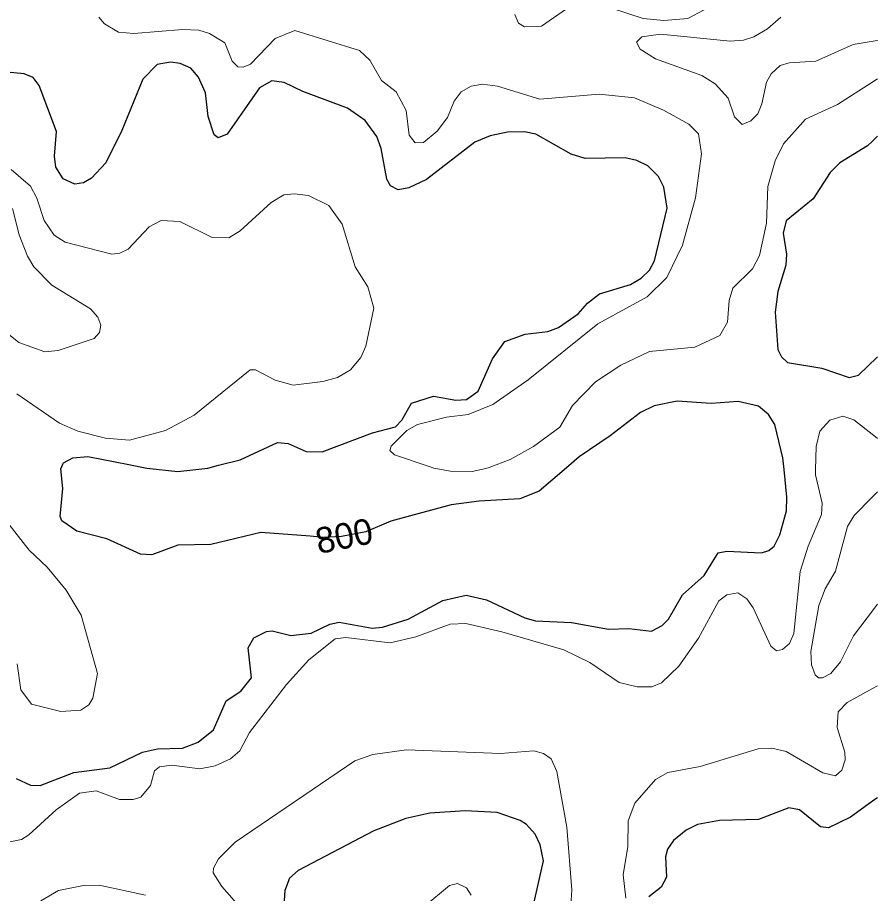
# Model space of a CAD drawing. Extents: x 473.9 to 500, y 7733.1 to 7760.8.
# Drawn here: x 497.324 to 500, y 7746.506 to 7749.235 of the extents above; entities that cross this region are included whole.
import ezdxf
from ezdxf.enums import TextEntityAlignment as Align

# ---------------------------------------------------------------- set-up
doc = ezdxf.new("R2010")
doc.units = 0
doc.header["$LTSCALE"] = 0.032
doc.layers.add('1', color=7, linetype='Continuous', lineweight=25)
doc.layers.add('2', color=7, linetype='Continuous', lineweight=13)
doc.layers.add('61', color=7, linetype='Continuous')

msp = doc.modelspace()

# ---------------------------------------------------------------- linework, layer by layer
at = {"layer": '1'}
for points in [[(498.5501, 7748.0341), (498.6184, 7748.0552), (498.6881, 7748.0425), (498.7206, 7748.0448), (498.7573, 7748.0715), (498.8019, 7748.1716), (498.8404, 7748.2256), (498.9036, 7748.2484), (498.9743, 7748.2573), (499.007, 7748.2694), (499.0683, 7748.3118), (499.0975, 7748.3454), (499.135, 7748.3746), (499.231, 7748.4035), (499.2642, 7748.4228), (499.2905, 7748.4477), (499.3063, 7748.4765), (499.3451, 7748.6413), (499.3349, 7748.7063), (499.3182, 7748.7392), (499.2848, 7748.7732), (499.2506, 7748.79), (499.2143, 7748.7974), (499.0906, 7748.7955), (499.0472, 7748.8097), (498.9367, 7748.8714), (498.9013, 7748.8786), (498.8484, 7748.8778), (498.7946, 7748.8663), (498.7464, 7748.8461), (498.5964, 7748.7308), (498.5417, 7748.7044), (498.5081, 7748.6981), (498.4845, 7748.7104), (498.4735, 7748.7311), (498.4556, 7748.8267), (498.4418, 7748.8647), (498.4053, 7748.9139), (498.3501, 7748.9525), (498.2112, 7749.0044), (498.1538, 7749.0324), (498.1156, 7749.0378), (498.0763, 7749.0163), (497.9761, 7748.8719), (497.9481, 7748.8606), (497.9357, 7748.8693), (497.917, 7748.927), (497.9089, 7748.9998), (497.8866, 7749.0491), (497.863, 7749.077), (497.8298, 7749.0918), (497.7995, 7749.0957), (497.7587, 7749.0885), (497.7139, 7749.043), (497.6485, 7748.8831), (497.5988, 7748.7822), (497.5538, 7748.734), (497.5285, 7748.7197), (497.5021, 7748.7156), (497.4654, 7748.7325), (497.4426, 7748.7687), (497.4389, 7748.803), (497.4446, 7748.8796), (497.3912, 7749.0233), (497.3719, 7749.0479), (497.3442, 7749.0592), (497.1383, 7749.0787)], [(500, 7748.8653), (499.9846, 7748.8499), (499.9694, 7748.8347), (499.8824, 7748.782), (499.8533, 7748.7524), (499.8002, 7748.6697), (499.7157, 7748.6016), (499.7069, 7748.5636), (499.7165, 7748.4973), (499.7143, 7748.4634), (499.6901, 7748.3817), (499.6821, 7748.3168), (499.6899, 7748.2007), (499.7011, 7748.1777), (499.7204, 7748.1606), (499.8272, 7748.1426), (499.9115, 7748.1141), (499.9412, 7748.1205), (499.9989, 7748.1768), (500, 7748.1779)], [(497.3198, 7746.8643), (497.3637, 7746.8436), (497.3945, 7746.8429), (497.4991, 7746.8838), (497.6111, 7746.8974), (497.713, 7746.9465), (497.7596, 7746.957), (497.8371, 7746.9592), (497.8863, 7746.9775), (497.9332, 7747.016), (497.9731, 7747.107), (498.0187, 7747.1364), (498.052, 7747.1785), (498.0413, 7747.2718), (498.0594, 7747.3031), (498.0985, 7747.3225), (498.1157, 7747.3243), (498.1739, 7747.3103), (498.2372, 7747.3173), (498.2954, 7747.345), (498.325, 7747.3517), (498.4274, 7747.3327), (498.4598, 7747.3359), (498.5391, 7747.361), (498.6478, 7747.4188), (498.7198, 7747.4361), (498.7829, 7747.4215), (498.9025, 7747.3655), (498.9361, 7747.356), (499.0473, 7747.3501), (499.1625, 7747.3301), (499.2258, 7747.3317), (499.2966, 7747.3235), (499.3302, 7747.341), (499.35, 7747.3605), (499.3933, 7747.4367), (499.4611, 7747.4966), (499.5043, 7747.5673), (499.5317, 7747.5729), (499.6388, 7747.5673), (499.6621, 7747.5746), (499.6785, 7747.5882), (499.6959, 7747.6233), (499.7174, 7747.6984), (499.7183, 7747.7405), (499.7095, 7747.8266), (499.7057, 7747.8636), (499.6809, 7747.9675), (499.6611, 7747.9982), (499.6302, 7748.0243), (499.5667, 7748.0391), (499.4829, 7748.0329), (499.3769, 7748.0396), (499.3046, 7748.0257), (499.2621, 7748.005), (499.1682, 7747.9316), (499.0719, 7747.866), (499.0317, 7747.8318), (498.9468, 7747.7597), (498.8873, 7747.7359), (498.7599, 7747.7289), (498.6731, 7747.7168), (498.4853, 7747.666), (498.4072, 7747.6331), (498.3322, 7747.6187), (498.2764, 7747.6148), (498.2345, 7747.6189), (498.0812, 7747.6308), (497.9255, 7747.5936), (497.8221, 7747.5915), (497.7416, 7747.5612), (497.7065, 7747.5633), (497.6011, 7747.6115), (497.5084, 7747.6349), (497.462, 7747.667), (497.4559, 7747.6807), (497.4645, 7747.7678), (497.4581, 7747.8287), (497.4646, 7747.8438), (497.4663, 7747.8478), (497.4958, 7747.8632), (497.5425, 7747.8679), (497.6701, 7747.8422), (497.7265, 7747.8309), (497.8225, 7747.8209), (497.9154, 7747.8316), (497.9496, 7747.8401), (498.0169, 7747.8568), (498.1325, 7747.9115), (498.1659, 7747.9082), (498.2217, 7747.8836), (498.2717, 7747.8826), (498.4281, 7747.9412), (498.5003, 7747.9602), (498.5195, 7747.9811), (498.5501, 7748.0341)], [(500, 7746.8047), (499.992, 7746.7989), (499.9156, 7746.7438), (499.8474, 7746.7113), (499.8227, 7746.7136), (499.757, 7746.7666), (499.7237, 7746.7729), (499.6295, 7746.7365), (499.5086, 7746.7335), (499.4397, 7746.7217), (499.4051, 7746.7037), (499.3653, 7746.6716), (499.3465, 7746.6449), (499.3406, 7746.6206), (499.3431, 7746.5572), (499.3263, 7746.5263), (499.2885, 7746.4964)], [(498.9159, 7746.4114), (498.9608, 7746.6081), (498.9502, 7746.6575), (498.9343, 7746.6917), (498.9082, 7746.721), (498.8885, 7746.7335), (498.8164, 7746.7587), (498.7167, 7746.764), (498.6067, 7746.757), (498.5326, 7746.7401), (498.4324, 7746.7016), (498.1974, 7746.5776), (498.1703, 7746.5541), (498.1559, 7746.5154), (498.1523, 7746.4693)]]:
    msp.add_lwpolyline(points, dxfattribs=at)
at = {"layer": '2'}
for points in [[(499.4609, 7749.259), (499.4101, 7749.232), (499.3353, 7749.2251), (499.2708, 7749.2323), (499.1244, 7749.2795)], [(499.0429, 7749.2694), (498.9543, 7749.2083), (498.9016, 7749.2054), (498.8832, 7749.2174), (498.8719, 7749.2441)], [(497.5764, 7749.2361), (497.5938, 7749.2152), (497.6375, 7749.1895), (497.6852, 7749.185), (497.8374, 7749.1977), (497.8883, 7749.1954), (497.921, 7749.1847), (497.9691, 7749.1563), (497.9914, 7749.0988), (498.0092, 7749.0809), (498.0257, 7749.0799), (498.0487, 7749.0897), (498.1255, 7749.1697), (498.1869, 7749.1945), (498.3882, 7749.1318), (498.4205, 7749.1021), (498.4567, 7749.0392), (498.5017, 7749.0038), (498.5329, 7748.9451), (498.5426, 7748.868), (498.5614, 7748.8444), (498.5868, 7748.846)], [(499.6997, 7749.2356), (499.6579, 7749.1991), (499.6147, 7749.1742), (499.5826, 7749.1643), (499.5413, 7749.1617), (499.3248, 7749.1826), (499.2663, 7749.175), (499.2496, 7749.1579), (499.2614, 7749.1362), (499.3093, 7749.1057), (499.453, 7749.0546), (499.495, 7749.0278), (499.5357, 7748.9839), (499.5551, 7748.9254), (499.5788, 7748.9021), (499.6057, 7748.9132), (499.6272, 7748.9344), (499.6402, 7748.9655), (499.6543, 7749.0336), (499.6688, 7749.0591), (499.6976, 7749.0857), (499.7247, 7749.0941), (499.8077, 7749.0992), (499.9241, 7749.1512), (499.9989, 7749.1633), (500, 7749.1635)], [(498.5868, 7748.846), (498.63, 7748.8806), (498.6623, 7748.9238), (498.683, 7748.974), (498.7042, 7749.0037), (498.7355, 7749.0213), (498.7709, 7749.0273), (498.8173, 7749.0214), (498.9496, 7748.9808), (499.1343, 7748.9961), (499.2438, 7748.9847), (499.3339, 7748.9461), (499.4132, 7748.9031), (499.4426, 7748.8725), (499.4522, 7748.8105), (499.4334, 7748.6732), (499.3928, 7748.5263), (499.3447, 7748.4253), (499.2828, 7748.3646), (499.1302, 7748.2808), (498.9127, 7748.1064), (498.8032, 7748.0293), (498.726, 7747.9983), (498.6585, 7747.9902), (498.5686, 7747.9668), (498.5351, 7747.9488), (498.4862, 7747.8998), (498.4825, 7747.8862), (498.4973, 7747.8732), (498.6082, 7747.8351), (498.6188, 7747.8314), (498.671, 7747.822), (498.7385, 7747.8207), (498.7813, 7747.8297), (498.7919, 7747.8336), (498.8569, 7747.8578), (498.9298, 7747.899), (499.0118, 7747.9585), (499.0511, 7748.0268), (499.122, 7748.0999), (499.2018, 7748.152), (499.2906, 7748.1944), (499.4319, 7748.2086), (499.5098, 7748.2442), (499.5331, 7748.2864), (499.538, 7748.3533), (499.5502, 7748.3914), (499.6114, 7748.4516), (499.6325, 7748.4939), (499.6547, 7748.594), (499.6592, 7748.7081), (499.6817, 7748.7882), (499.7075, 7748.8415), (499.7757, 7748.9184), (499.8753, 7748.9644), (499.982, 7749.0323), (500, 7749.0438)], [(497.3212, 7748.0631), (497.4541, 7747.9713), (497.5111, 7747.946), (497.5976, 7747.9249), (497.6724, 7747.9187), (497.7846, 7747.9486), (497.8733, 7747.9964), (498.0475, 7748.1379), (498.0639, 7748.1371), (498.1252, 7748.1057), (498.1814, 7748.09), (498.274, 7748.1008), (498.3197, 7748.1137), (498.3599, 7748.1377), (498.3916, 7748.1759), (498.4079, 7748.2109), (498.4327, 7748.3299), (498.4139, 7748.3965), (498.3745, 7748.4583), (498.3345, 7748.5907), (498.2927, 7748.6495), (498.2292, 7748.68), (498.1847, 7748.6856), (498.1522, 7748.6822), (498.1128, 7748.6583), (498.0168, 7748.5708), (497.9813, 7748.5491), (497.9299, 7748.55), (497.8288, 7748.5996), (497.7711, 7748.6028), (497.7338, 7748.5832), (497.668, 7748.5129), (497.6421, 7748.5005), (497.6171, 7748.4976), (497.4719, 7748.5349), (497.4378, 7748.5572), (497.4061, 7748.6031), (497.3839, 7748.6718), (497.364, 7748.7098), (497.304, 7748.7612)], [(497.3079, 7748.6401), (497.3283, 7748.5581), (497.3542, 7748.4917), (497.3748, 7748.4582), (497.4303, 7748.4009), (497.5506, 7748.327), (497.5736, 7748.3018), (497.5827, 7748.2762), (497.5785, 7748.2539), (497.5619, 7748.2349), (497.4503, 7748.1979), (497.4081, 7748.1937), (497.3282, 7748.2228), (497.2405, 7748.2919)], [(500, 7747.9238), (499.9882, 7747.9332), (499.9269, 7747.9818), (499.892, 7747.9934), (499.8513, 7747.981), (499.8207, 7747.9466), (499.8089, 7747.8982), (499.8072, 7747.8259), (499.8068, 7747.8109), (499.8282, 7747.7224), (499.8261, 7747.6866), (499.7844, 7747.5879), (499.759, 7747.5091), (499.7398, 7747.3167), (499.7262, 7747.2852), (499.704, 7747.2665), (499.686, 7747.2621), (499.668, 7747.2766), (499.6128, 7747.396), (499.5932, 7747.4238), (499.5657, 7747.4434), (499.5313, 7747.4367), (499.5059, 7747.4177), (499.4431, 7747.3012), (499.382, 7747.2145), (499.3274, 7747.1621), (499.2975, 7747.1497), (499.2519, 7747.1501), (499.1966, 7747.1641), (499.1049, 7747.2257), (499.0241, 7747.2655), (498.8311, 7747.3219), (498.7191, 7747.3479), (498.6698, 7747.3449), (498.5631, 7747.3056), (498.4838, 7747.2876), (498.3449, 7747.3034), (498.3118, 7747.2995), (498.2305, 7747.2341), (498.1604, 7747.1579), (498.0457, 7747.0084), (498.0158, 7746.9503), (497.9862, 7746.926), (497.9387, 7746.9044), (497.8915, 7746.8952), (497.8041, 7746.9064), (497.7655, 7746.901), (497.7503, 7746.8885), (497.7376, 7746.8428), (497.7074, 7746.8064), (497.6835, 7746.7989), (497.6412, 7746.7989), (497.5683, 7746.8262), (497.5168, 7746.8187), (497.4441, 7746.7675), (497.3588, 7746.6891), (497.3356, 7746.6749), (497.2992, 7746.6669)], [(500, 7747.7578), (499.9838, 7747.7411), (499.928, 7747.6837), (499.9064, 7747.6499), (499.8696, 7747.5104), (499.8372, 7747.4556), (499.8179, 7747.4036), (499.7931, 7747.2598), (499.7947, 7747.2191), (499.8066, 7747.1871), (499.8166, 7747.1785), (499.8287, 7747.1782), (499.8549, 7747.1912), (499.8847, 7747.2279), (499.9257, 7747.3092), (499.9909, 7747.3953), (500, 7747.4073)], [(497.3222, 7747.2221), (497.3339, 7747.1408), (497.3673, 7747.0966), (497.4585, 7747.0735), (497.5206, 7747.0771), (497.5451, 7747.0939), (497.5578, 7747.1147), (497.573, 7747.1916), (497.5215, 7747.3735), (497.4748, 7747.4516), (497.4155, 7747.523), (497.3602, 7747.5755), (497.2707, 7747.6903)], [(499.4486, 7746.9017), (499.6284, 7746.9572), (499.671, 7746.9586), (499.7155, 7746.9485), (499.8298, 7746.882), (499.8695, 7746.8733), (499.8893, 7746.8906), (499.8998, 7746.9227), (499.898, 7746.947), (499.8742, 7747.0235), (499.8778, 7747.0719), (499.9052, 7747.1018), (499.9844, 7747.1445), (500, 7747.1529)], [(498.0133, 7746.4671), (497.9599, 7746.5281), (497.9329, 7746.5705), (497.9331, 7746.5851), (497.9494, 7746.6145), (498.0015, 7746.6661), (498.3732, 7746.9192), (498.4292, 7746.9395), (498.5342, 7746.9537), (498.8268, 7746.9426), (498.9303, 7746.9506), (498.9603, 7746.9428), (498.9846, 7746.926), (499.0023, 7746.8859), (499.0332, 7746.7126), (499.0484, 7746.518), (499.0405, 7746.385)], [(499.2166, 7746.4922), (499.2085, 7746.5643), (499.2228, 7746.6525), (499.2237, 7746.733), (499.2444, 7746.7877), (499.309, 7746.8612), (499.3473, 7746.8832), (499.4486, 7746.9017)], [(497.3958, 7746.4831), (497.4511, 7746.5162), (497.5287, 7746.5318), (497.5777, 7746.5319), (497.7216, 7746.5011)], [(498.7359, 7746.5015), (498.721, 7746.5238), (498.6933, 7746.538), (498.6685, 7746.531), (498.5882, 7746.465)]]:
    msp.add_lwpolyline(points, dxfattribs=at)

# ---------------------------------------------------------------- texts
at = {"layer": '61'}
msp.add_text('800', height=0.08, rotation=11.31, dxfattribs=at).set_placement((498.3479, 7747.5811), align=Align.CENTER)

doc.saveas('drawing.dxf')
